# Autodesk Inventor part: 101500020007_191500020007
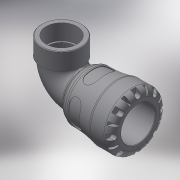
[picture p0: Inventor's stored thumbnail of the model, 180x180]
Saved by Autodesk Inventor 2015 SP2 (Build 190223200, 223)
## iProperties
Created: 2016-12
Part Number: 101500020007_191500020007
Material: Generic
Description: PLASSON 90° ELBOW WITH THREADED FEMALE OFFTAKE 20X3/4" SERIES 1
Document SubType Name: Modeling
Designer: KIM
Mass: 557.611 g
Surface Area: 990.043 cm^2
Volume: 557.611 cm^3
Density: 1 g/cm^3
Appearance: Default
Author: KIM
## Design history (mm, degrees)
derived "1015.ipt"
feature "Solid1::1015.ipt"
tag "TaggingFeature1"
body "Solid1"
other parameters: "d1" = 18.9, "d3" = 25, "d4" = 41, "d8" = 36.08, "d13" = 6.4, "d14" = 6.4, "d15" = 0, "d17" = 360 deg, "d19" = 8 deg, "d20" = 0.4, "d21" = 0.4, "d22" = 8 deg, "d24" = 0, "d26" = 360 deg, "d33" = 4.1, "d43" = 33.62, "d51" = 0.41, "d54" = 7, "d55" = 4.4, "d57" = 12.544, "d58" = 0, "d74" = 0, "d78" = 45, "d82" = 0.4, "d115" = 360 deg, "d207" = 90 deg, "d228" = 5.95, "d247" = 0.82, "d248" = 2.7, "d268" = 19.844, "d269" = 2.7, "d270" = 67, "d279" = 43, "d281" = 3.61755, "d294" = 24.117, "d295" = 18, "d296" = 19.8, "d297" = 21.7053, "d299" = 28.21689, "d300" = 21.7053, "d301" = 0, "d302" = 0, "d303" = 2.70155, "d306" = 0, "d307" = 9, "d308" = 8, "d310" = 3, "E_" = 41, "l_" = 45, "A_" = 67, "A_1" = 43, "l_2" = 18, "Rp_" = 24.117, "d9" = 8, "d11" = 41, "d12" = 25, "d298" = 31.3521
